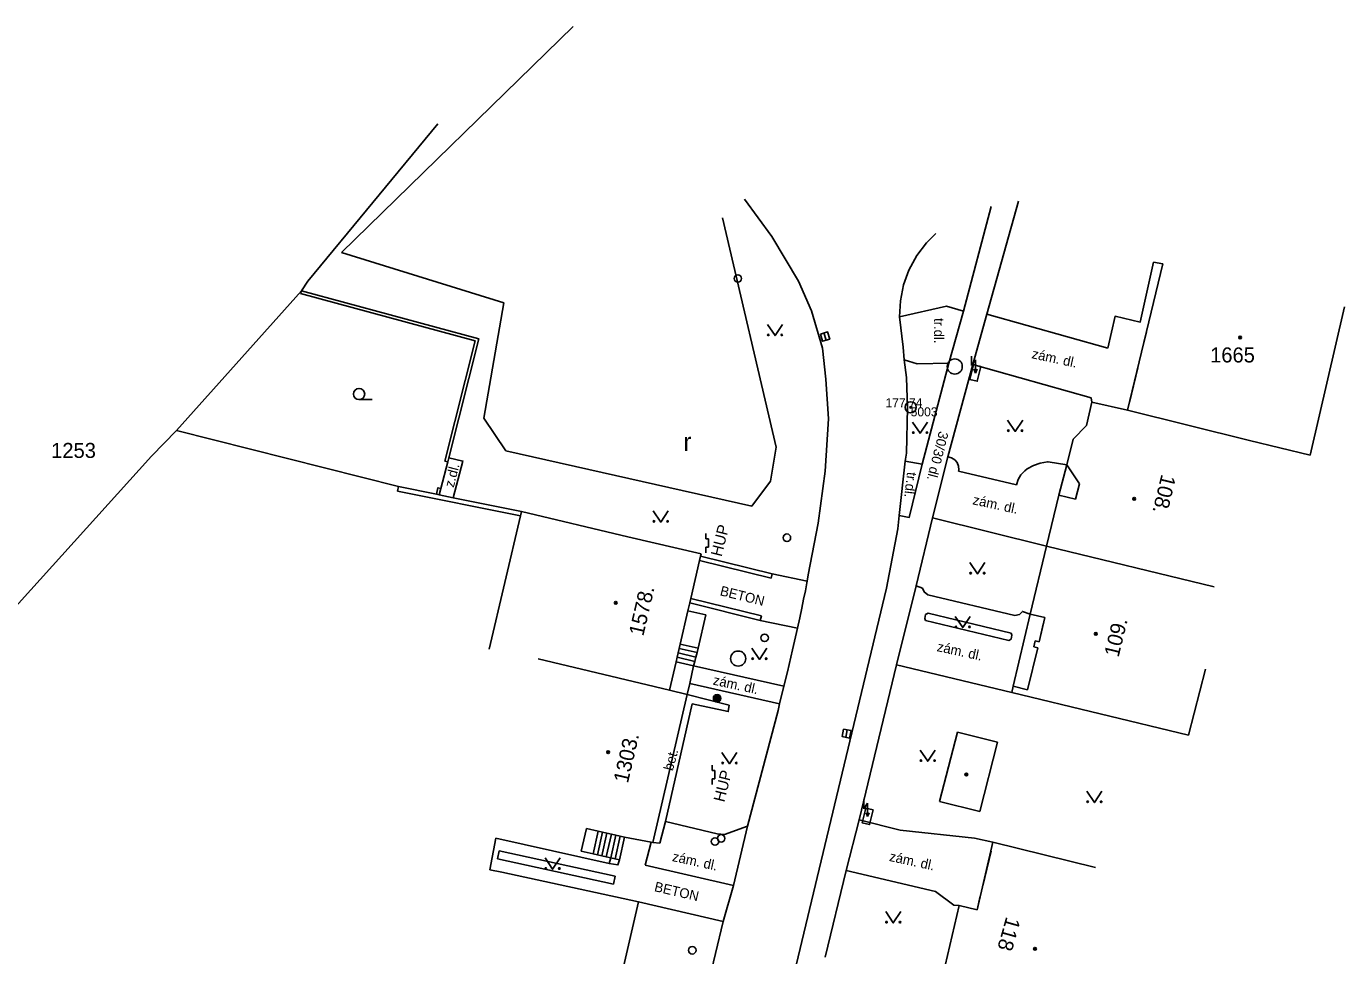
# Model space of a CAD drawing. Extents: x -540235 to -537963, y -1184915 to -1183660.
# Drawn here: x -538224.4 to -538136.8, y -1183806.3 to -1183744.6 of the extents above; entities that cross this region are included whole.
import ezdxf

# ---------------------------------------------------------------- set-up
doc = ezdxf.new("R2010")
doc.units = 0
for name, color, linetype in [('Vrstva 10', 7, 'Continuous'), ('Vrstva 11', 7, 'Continuous'), ('Vrstva 21', 7, 'Continuous'), ('Vrstva 22', 7, 'Continuous'), ('Vrstva 23', 7, 'Continuous'), ('Vrstva 24', 7, 'Continuous'), ('Vrstva 25', 7, 'Continuous'), ('Vrstva 27', 7, 'Continuous'), ('Vrstva 28', 7, 'Continuous'), ('Vrstva 36', 7, 'Continuous'), ('Vrstva 39', 7, 'Continuous'), ('Vrstva 40', 7, 'Continuous'), ('Vrstva 41', 7, 'Continuous'), ('Vrstva 47', 7, 'Continuous'), ('Vrstva 5', 7, 'Continuous'), ('Vrstva 6', 7, 'Continuous'), ('Vrstva 7', 7, 'Continuous'), ('Vrstva 8', 7, 'Continuous')]:
    doc.layers.add(name, color=color, linetype=linetype)

msp = doc.modelspace()

# ---------------------------------------------------------------- linework, layer by layer
at = {"layer": 'Vrstva 10'}
for p, q in [((-538171.1, -1183770.66), (-538171.32, -1183774.15)), ((-538166.39, -1183777.09), (-538165.99, -1183773.49)), ((-538167.23, -1183781.93), (-538173.25, -1183806.97)), ((-538176.48, -1183797.74), (-538177.4, -1183801.69)), ((-538177.4, -1183801.69), (-538178.1, -1183804.07)), ((-538178.1, -1183804.07), (-538180.3, -1183813.22))]:
    msp.add_line(p, q, dxfattribs=at)
for points in [[(-538176.67, -1183756.07), (-538174.86, -1183758.55), (-538173.09, -1183761.51), (-538172.22, -1183763.48)], [(-538166.37, -1183763.88), (-538166.317, -1183762.812), (-538166.105, -1183761.763), (-538165.75, -1183760.78), (-538165.229, -1183759.818), (-538164.584, -1183758.965), (-538163.96, -1183758.34)], [(-538172.22, -1183763.48), (-538171.5, -1183765.96), (-538171.26, -1183768.02), (-538171.1, -1183770.66)], [(-538166.37, -1183763.88), (-538166.14, -1183765.91), (-538166.06, -1183766.75)], [(-538166.06, -1183766.75), (-538165.9, -1183767.91), (-538165.85, -1183769.93), (-538165.91, -1183772.95), (-538165.99, -1183773.49)], [(-538171.32, -1183774.15), (-538171.78, -1183777.6), (-538172.44, -1183781.03)], [(-538166.39, -1183777.09), (-538166.49, -1183777.98), (-538167.23, -1183781.93)], [(-538173.83, -1183787.474), (-538173.493, -1183786.023), (-538173.16, -1183784.57), (-538173.008, -1183783.893), (-538172.87, -1183783.257), (-538172.745, -1183782.661), (-538172.631, -1183782.1), (-538172.527, -1183781.574), (-538172.503, -1183781.45), (-538172.44, -1183781.03)], [(-538174.451, -1183790.053), (-538174.343, -1183789.606), (-538174.06, -1183788.44), (-538173.83, -1183787.474)], [(-538176.48, -1183797.74), (-538174.451, -1183790.053)]]:
    msp.add_lwpolyline(points, dxfattribs=at)
at = {"layer": 'Vrstva 11'}
for p, q in [((-538158.47, -1183756.19), (-538160.57, -1183763.71)), ((-538162.11, -1183763.5), (-538160.29, -1183756.56)), ((-538163.1, -1183766.97), (-538162.11, -1183763.5)), ((-538160.57, -1183763.71), (-538161.5, -1183767.06)), ((-538160.57, -1183763.71), (-538152.53, -1183765.96)), ((-538164.87, -1183773.69), (-538163.1, -1183766.97)), ((-538163.16, -1183773.19), (-538161.5, -1183767.06)), ((-538161.5, -1183767.06), (-538153.63, -1183769.27)), ((-538153.63, -1183769.27), (-538153.59, -1183769.55)), ((-538165.99, -1183773.49), (-538164.87, -1183773.69)), ((-538164.19, -1183777.24), (-538163.16, -1183773.19)), ((-538155.257, -1183773.725), (-538156.49, -1183773.53)), ((-538162.45, -1183774.14), (-538158.6, -1183775.06)), ((-538164.19, -1183777.24), (-538165.27, -1183781.77)), ((-538156.61, -1183779.12), (-538164.19, -1183777.24)), ((-538172.503, -1183781.45), (-538174.83, -1183780.97)), ((-538165.27, -1183781.77), (-538166.57, -1183787.02)), ((-538158.71, -1183783.74), (-538164.48, -1183782.36)), ((-538180.439, -1183783.421), (-538179.24, -1183783.7)), ((-538164.46, -1183783.58), (-538158.94, -1183784.91)), ((-538173.16, -1183784.57), (-538175.63, -1183784.06)), ((-538159.1, -1183785.39), (-538164.64, -1183784.07)), ((-538181.022, -1183785.932), (-538179.835, -1183786.208)), ((-538180.954, -1183785.64), (-538179.767, -1183785.916)), ((-538181.226, -1183786.809), (-538180.06, -1183787.08)), ((-538181.158, -1183786.516), (-538179.971, -1183786.792)), ((-538181.09, -1183786.224), (-538179.903, -1183786.5)), ((-538180.06, -1183787.08), (-538174.06, -1183788.44)), ((-538166.57, -1183787.02), (-538169.06, -1183797.32)), ((-538158.91, -1183788.86), (-538166.57, -1183787.02)), ((-538180.311, -1183788.253), (-538174.343, -1183789.606)), ((-538181.94, -1183797.44), (-538180.16, -1183789.6)), ((-538182.3, -1183798.88), (-538181.94, -1183797.44)), ((-538169.06, -1183797.32), (-538169.93, -1183800.68)), ((-538186.405, -1183798.082), (-538186.745, -1183799.582)), ((-538186.113, -1183798.148), (-538186.453, -1183799.648)), ((-538185.82, -1183798.215), (-538186.16, -1183799.715)), ((-538185.528, -1183798.281), (-538185.868, -1183799.781)), ((-538185.235, -1183798.347), (-538185.575, -1183799.847)), ((-538184.943, -1183798.414), (-538185.283, -1183799.914)), ((-538184.99, -1183799.98), (-538184.65, -1183798.48)), ((-538193.1, -1183799.92), (-538192.98, -1183799.37)), ((-538192.98, -1183799.37), (-538185.28, -1183801.06)), ((-538183.28, -1183800.33), (-538182.89, -1183798.8)), ((-538182.77, -1183798.83), (-538182.3, -1183798.88)), ((-538185.39, -1183801.59), (-538193.1, -1183799.92)), ((-538185.28, -1183801.06), (-538185.39, -1183801.59)), ((-538177.4, -1183801.69), (-538183.28, -1183800.33)), ((-538169.93, -1183800.68), (-538171.31, -1183806.45)), ((-538163.98, -1183802.09), (-538169.93, -1183800.68)), ((-538178.1, -1183804.07), (-538183.72, -1183802.77))]:
    msp.add_line(p, q, dxfattribs=at)
for points in [[(-538152.53, -1183765.96), (-538152.04, -1183763.85), (-538150.37, -1183764.24), (-538149.48, -1183760.26), (-538148.87, -1183760.36)], [(-538166.37, -1183763.88), (-538163.24, -1183763.18), (-538162.11, -1183763.5)], [(-538163.1, -1183766.97), (-538165.21, -1183767.01), (-538166.06, -1183766.75)], [(-538196.34, -1183773.25), (-538195.4, -1183773.47), (-538196.04, -1183775.91)], [(-538166.39, -1183777.09), (-538165.73, -1183777.22), (-538164.87, -1183773.69)], [(-538163.16, -1183773.19), (-538162.917, -1183773.248), (-538162.704, -1183773.38), (-538162.543, -1183773.571), (-538162.451, -1183773.804), (-538162.436, -1183774.053), (-538162.45, -1183774.14)], [(-538157.88, -1183773.99), (-538157.463, -1183773.763), (-538157.014, -1183773.61), (-538156.545, -1183773.534), (-538156.49, -1183773.53)], [(-538158.6, -1183775.06), (-538158.486, -1183774.708), (-538158.299, -1183774.39), (-538158.047, -1183774.118), (-538157.88, -1183773.99)], [(-538164.48, -1183782.36), (-538164.73, -1183782.17), (-538164.85, -1183781.91), (-538165.27, -1183781.77)], [(-538164.64, -1183784.07), (-538164.7, -1183783.93), (-538164.64, -1183783.68), (-538164.46, -1183783.58)], [(-538157.68, -1183783.65), (-538158.2, -1183783.47), (-538158.39, -1183783.67), (-538158.71, -1183783.74)], [(-538179.24, -1183783.7), (-538179.767, -1183785.916), (-538179.835, -1183786.208), (-538179.903, -1183786.5), (-538179.971, -1183786.792), (-538180.06, -1183787.08)], [(-538158.94, -1183784.91), (-538158.9, -1183785.05), (-538158.95, -1183785.3), (-538159.1, -1183785.39)], [(-538180.48, -1183788.98), (-538180.311, -1183788.253), (-538180.06, -1183787.08)], [(-538180.16, -1183789.6), (-538177.76, -1183790.12), (-538177.7, -1183789.7), (-538180.48, -1183788.98)], [(-538176.48, -1183797.74), (-538178, -1183798.3), (-538178.49, -1183798.24), (-538181.94, -1183797.44)], [(-538169.06, -1183797.32), (-538166.33, -1183798), (-538161.38, -1183798.54), (-538160.16, -1183798.8)], [(-538162.41, -1183803.01), (-538162.77, -1183802.99), (-538163.98, -1183802.09)]]:
    msp.add_lwpolyline(points, dxfattribs=at)
at = {"layer": 'Vrstva 21'}
for radius in [0.375, 0.05]:
    msp.add_circle((-538165.63, -1183769.9), radius, dxfattribs=at)
at = {"layer": 'Vrstva 23'}
for p, q in [((-538188.06, -1183744.58), (-538203.46, -1183759.62)), ((-538174.57, -1183772.54), (-538178.14, -1183757.31)), ((-538203.46, -1183759.62), (-538192.67, -1183762.96)), ((-538192.67, -1183762.96), (-538194.01, -1183770.63)), ((-538194.01, -1183770.63), (-538192.55, -1183772.79)), ((-538192.55, -1183772.79), (-538176.19, -1183776.48))]:
    msp.add_line(p, q, dxfattribs=at)
msp.add_lwpolyline([(-538176.19, -1183776.48), (-538174.94, -1183774.81), (-538174.57, -1183772.54)], dxfattribs=at)
at = {"layer": 'Vrstva 24'}
for p, q in [((-538161.58, -1183766.494), (-538161.58, -1183767.12)), ((-538161.58, -1183767.12), (-538161.33, -1183766.745)), ((-538161.33, -1183766.745), (-538161.33, -1183767.62)), ((-538161.44, -1183767.375), (-538161.33, -1183767.62)), ((-538161.33, -1183767.62), (-538161.22, -1183767.375)), ((-538179.249, -1183778.649), (-538179.25, -1183778.281)), ((-538179.25, -1183779.57), (-538179.249, -1183779.202)), ((-538179.066, -1183778.65), (-538179.249, -1183778.649)), ((-538179.249, -1183779.202), (-538179.066, -1183779.202)), ((-538179.066, -1183779.202), (-538179.066, -1183778.65)), ((-538178.829, -1183794.049), (-538178.83, -1183793.681)), ((-538178.646, -1183794.05), (-538178.829, -1183794.049)), ((-538178.646, -1183794.602), (-538178.646, -1183794.05)), ((-538178.83, -1183794.97), (-538178.829, -1183794.602)), ((-538178.829, -1183794.602), (-538178.646, -1183794.602)), ((-538168.74, -1183795.964), (-538168.74, -1183796.59)), ((-538168.74, -1183796.59), (-538168.49, -1183796.215)), ((-538168.49, -1183796.215), (-538168.49, -1183797.09)), ((-538168.6, -1183796.845), (-538168.49, -1183797.09)), ((-538168.49, -1183797.09), (-538168.38, -1183796.845))]:
    msp.add_line(p, q, dxfattribs=at)
for points in [[(-538161.453, -1183767.075), (-538161.692, -1183768.046), (-538161.207, -1183768.165), (-538160.968, -1183767.194)], [(-538168.619, -1183796.546), (-538168.848, -1183797.519), (-538168.361, -1183797.634), (-538168.132, -1183796.661)]]:
    msp.add_lwpolyline(points, close=True, dxfattribs=at)
at = {"layer": 'Vrstva 25'}
for radius in [0.25, 0.2, 0.15, 0.1, 0.05]:
    msp.add_circle((-538178.5, -1183789.24), radius, dxfattribs=at)
at = {"layer": 'Vrstva 27'}
for p, q in [((-538171.396, -1183764.96), (-538171.244, -1183765.436)), ((-538169.843, -1183791.344), (-538169.937, -1183791.836))]:
    msp.add_line(p, q, dxfattribs=at)
for points in [[(-538171.634, -1183765.036), (-538171.482, -1183765.512), (-538171.006, -1183765.36), (-538171.158, -1183764.884)], [(-538170.088, -1183791.297), (-538170.183, -1183791.788), (-538169.692, -1183791.883), (-538169.597, -1183791.392)]]:
    msp.add_lwpolyline(points, close=True, dxfattribs=at)
for centre in [(-538162.699, -1183767.188), (-538177.1, -1183786.6)]:
    msp.add_circle(centre, 0.5, dxfattribs=at)
at = {"layer": 'Vrstva 28'}
for centre in [(-538177.12, -1183761.34), (-538173.86, -1183778.57), (-538175.34, -1183785.22), (-538178.23, -1183798.55), (-538178.64, -1183798.76), (-538180.15, -1183805.99)]:
    msp.add_circle(centre, 0.25, dxfattribs=at)
at = {"layer": 'Vrstva 36'}
msp.add_line((-538202.303, -1183769.391), (-538201.428, -1183769.391), dxfattribs=at)
for points in [[(-538175.149, -1183764.385), (-538174.649, -1183765.135), (-538174.149, -1183764.385)], [(-538165.502, -1183770.878), (-538165.002, -1183771.628), (-538164.502, -1183770.878)], [(-538159.183, -1183770.754), (-538158.683, -1183771.504), (-538158.183, -1183770.754)], [(-538182.743, -1183776.783), (-538182.243, -1183777.533), (-538181.743, -1183776.783)], [(-538161.695, -1183780.222), (-538161.195, -1183780.972), (-538160.695, -1183780.222)], [(-538162.669, -1183783.795), (-538162.169, -1183784.545), (-538161.669, -1183783.795)], [(-538176.188, -1183785.911), (-538175.688, -1183786.661), (-538175.188, -1183785.911)], [(-538178.177, -1183792.846), (-538177.677, -1183793.596), (-538177.177, -1183792.846)], [(-538164.992, -1183792.678), (-538164.492, -1183793.428), (-538163.992, -1183792.678)], [(-538153.915, -1183795.42), (-538153.415, -1183796.17), (-538152.915, -1183795.42)], [(-538189.938, -1183799.853), (-538189.438, -1183800.603), (-538188.938, -1183799.853)], [(-538167.286, -1183803.42), (-538166.786, -1183804.17), (-538166.286, -1183803.42)]]:
    msp.add_lwpolyline(points, dxfattribs=at)
for centre, radius in [((-538175.0992, -1183765.0848), 0.05), ((-538174.1998, -1183765.0848), 0.05), ((-538202.3031, -1183769.0159), 0.375), ((-538165.4522, -1183771.5778), 0.05), ((-538164.5528, -1183771.5778), 0.05), ((-538159.1332, -1183771.4538), 0.05), ((-538158.2338, -1183771.4538), 0.05), ((-538182.6932, -1183777.4828), 0.05), ((-538181.7938, -1183777.4828), 0.05), ((-538161.6452, -1183780.9218), 0.05), ((-538160.7458, -1183780.9218), 0.05), ((-538162.6192, -1183784.4948), 0.05), ((-538161.7198, -1183784.4948), 0.05), ((-538176.1382, -1183786.6108), 0.05), ((-538175.2388, -1183786.6108), 0.05), ((-538178.1272, -1183793.5458), 0.05), ((-538177.2278, -1183793.5458), 0.05), ((-538164.9422, -1183793.3778), 0.05), ((-538164.0428, -1183793.3778), 0.05), ((-538153.8652, -1183796.1198), 0.05), ((-538152.9658, -1183796.1198), 0.05), ((-538189.8882, -1183800.5528), 0.05), ((-538188.9888, -1183800.5528), 0.05), ((-538167.2362, -1183804.1198), 0.05), ((-538166.3368, -1183804.1198), 0.05)]:
    msp.add_circle(centre, radius, dxfattribs=at)
at = {"layer": 'Vrstva 39'}
for centre, radius in [((-538143.729, -1183765.267), 0.09), ((-538143.729, -1183765.267), 0.0398), ((-538150.765, -1183775.983), 0.09), ((-538150.765, -1183775.983), 0.0398), ((-538185.241, -1183782.892), 0.09), ((-538185.241, -1183782.892), 0.0398), ((-538153.328, -1183784.961), 0.09), ((-538153.328, -1183784.961), 0.0398), ((-538185.748, -1183792.826), 0.09), ((-538185.748, -1183792.826), 0.0398), ((-538161.93, -1183794.312), 0.09), ((-538161.93, -1183794.312), 0.0398), ((-538157.366, -1183805.892), 0.09), ((-538157.366, -1183805.892), 0.0398)]:
    msp.add_circle(centre, radius, dxfattribs=at)
at = {"layer": 'Vrstva 5'}
for p, q in [((-538148.87, -1183760.36), (-538151.21, -1183770.09)), ((-538139.07, -1183773.09), (-538136.78, -1183763.22)), ((-538153.942, -1183771.103), (-538153.59, -1183769.55)), ((-538153.59, -1183769.55), (-538151.21, -1183770.09)), ((-538151.21, -1183770.09), (-538143.1, -1183772.11)), ((-538154.82, -1183772.02), (-538153.942, -1183771.103)), ((-538154.82, -1183772.02), (-538155.257, -1183773.725)), ((-538143.1, -1183772.11), (-538139.07, -1183773.09)), ((-538155.77, -1183775.73), (-538155.257, -1183773.725)), ((-538155.257, -1183773.725), (-538154.411, -1183774.979)), ((-538155.77, -1183775.73), (-538156.61, -1183779.12)), ((-538154.675, -1183776.01), (-538155.77, -1183775.73)), ((-538193.66, -1183785.98), (-538191.575, -1183777.112)), ((-538191.575, -1183777.112), (-538191.5, -1183776.82)), ((-538191.5, -1183776.82), (-538184.43, -1183778.508)), ((-538184.43, -1183778.508), (-538179.56, -1183779.64)), ((-538156.61, -1183779.12), (-538157.68, -1183783.65)), ((-538145.45, -1183781.83), (-538156.61, -1183779.12)), ((-538180.249, -1183782.602), (-538179.662, -1183780.078)), ((-538179.662, -1183780.078), (-538179.593, -1183779.786)), ((-538179.593, -1183779.786), (-538179.56, -1183779.64)), ((-538180.317, -1183782.895), (-538180.249, -1183782.602)), ((-538180.954, -1183785.64), (-538180.439, -1183783.421)), ((-538180.439, -1183783.421), (-538180.317, -1183782.895)), ((-538156.707, -1183783.88), (-538157.68, -1183783.65)), ((-538157.08, -1183785.49), (-538156.707, -1183783.88)), ((-538181.09, -1183786.224), (-538181.022, -1183785.932)), ((-538181.022, -1183785.932), (-538180.954, -1183785.64)), ((-538157.86, -1183788.67), (-538157.167, -1183785.891)), ((-538157.44, -1183785.83), (-538157.35, -1183785.43)), ((-538157.167, -1183785.891), (-538157.44, -1183785.83)), ((-538157.35, -1183785.43), (-538157.08, -1183785.49)), ((-538190.39, -1183786.62), (-538181.667, -1183788.704)), ((-538181.667, -1183788.704), (-538181.226, -1183786.809)), ((-538181.226, -1183786.809), (-538181.158, -1183786.516)), ((-538181.158, -1183786.516), (-538181.09, -1183786.224)), ((-538147.15, -1183791.69), (-538146.04, -1183787.3)), ((-538181.667, -1183788.704), (-538180.48, -1183788.98)), ((-538158.812, -1183788.445), (-538157.86, -1183788.67)), ((-538182.77, -1183798.83), (-538180.48, -1183788.98)), ((-538158.91, -1183788.86), (-538147.15, -1183791.69)), ((-538162.52, -1183791.5), (-538163.71, -1183796.11)), ((-538159.85, -1183792.16), (-538162.52, -1183791.5)), ((-538161.04, -1183796.77), (-538159.85, -1183792.16)), ((-538163.71, -1183796.11), (-538161.04, -1183796.77)), ((-538187.526, -1183799.405), (-538187.186, -1183797.905)), ((-538187.186, -1183797.905), (-538186.405, -1183798.082)), ((-538186.113, -1183798.148), (-538186.405, -1183798.082)), ((-538185.82, -1183798.215), (-538186.113, -1183798.148)), ((-538185.528, -1183798.281), (-538185.82, -1183798.215)), ((-538185.235, -1183798.347), (-538185.528, -1183798.281)), ((-538184.943, -1183798.414), (-538185.235, -1183798.347)), ((-538184.65, -1183798.48), (-538184.943, -1183798.414)), ((-538184.65, -1183798.48), (-538182.89, -1183798.8)), ((-538185.67, -1183800.22), (-538193.2, -1183798.54)), ((-538182.89, -1183798.8), (-538182.77, -1183798.83)), ((-538160.16, -1183798.8), (-538161.22, -1183803.291)), ((-538153.35, -1183800.49), (-538160.16, -1183798.8)), ((-538186.745, -1183799.582), (-538187.526, -1183799.405)), ((-538186.453, -1183799.648), (-538186.745, -1183799.582)), ((-538186.16, -1183799.715), (-538186.453, -1183799.648)), ((-538185.868, -1183799.781), (-538186.16, -1183799.715)), ((-538185.575, -1183799.847), (-538185.868, -1183799.781)), ((-538185.575, -1183799.847), (-538185.67, -1183800.22)), ((-538192.82, -1183800.8), (-538183.72, -1183802.77)), ((-538162.41, -1183803.01), (-538163.66, -1183808.33)), ((-538161.22, -1183803.291), (-538162.41, -1183803.01))]:
    msp.add_line(p, q, dxfattribs=at)
for points in [[(-538157.68, -1183783.65), (-538158.812, -1183788.445)], [(-538158.812, -1183788.445), (-538158.91, -1183788.86)], [(-538183.72, -1183802.77), (-538185.84, -1183811.89)]]:
    msp.add_lwpolyline(points, dxfattribs=at)
at = {"layer": 'Vrstva 6'}
for p, q in [((-538149.96, -1183764.91), (-538150.21, -1183765.94)), ((-538150.53, -1183767.27), (-538151.09, -1183769.58)), ((-538154.411, -1183774.979), (-538154.675, -1183776.01)), ((-538156.79, -1183784.23), (-538157.08, -1183785.49)), ((-538157.167, -1183785.891), (-538157.86, -1183788.67)), ((-538160.29, -1183799.4), (-538160.83, -1183801.7)), ((-538161.01, -1183802.4), (-538161.22, -1183803.291))]:
    msp.add_line(p, q, dxfattribs=at)
at = {"layer": 'Vrstva 7'}
for p, q in [((-538197.074, -1183751.062), (-538205.71, -1183761.51)), ((-538206.14, -1183762.15), (-538205.71, -1183761.51)), ((-538214.45, -1183771.45), (-538206.14, -1183762.15)), ((-538206.14, -1183762.15), (-538206.192, -1183762.343)), ((-538206.192, -1183762.343), (-538194.592, -1183765.482)), ((-538206.14, -1183762.15), (-538194.35, -1183765.34)), ((-538194.592, -1183765.482), (-538196.604, -1183773.471)), ((-538194.35, -1183765.34), (-538196.34, -1183773.25)), ((-538214.45, -1183771.45), (-538216.1, -1183773.14)), ((-538199.687, -1183775.174), (-538214.45, -1183771.45)), ((-538216.1, -1183773.14), (-538306.52, -1183873.14)), ((-538196.604, -1183773.471), (-538196.41, -1183773.52)), ((-538196.34, -1183773.25), (-538196.41, -1183773.52)), ((-538199.687, -1183775.174), (-538199.746, -1183775.468)), ((-538199.746, -1183775.468), (-538191.575, -1183777.112)), ((-538196.87, -1183775.29), (-538196.97, -1183775.72)), ((-538174.902, -1183781.261), (-538179.662, -1183780.078)), ((-538174.83, -1183780.97), (-538179.593, -1183779.786)), ((-538174.902, -1183781.261), (-538174.83, -1183780.97)), ((-538175.557, -1183783.768), (-538180.249, -1183782.602)), ((-538175.63, -1183784.06), (-538180.317, -1183782.895)), ((-538175.63, -1183784.06), (-538175.557, -1183783.768)), ((-538193.62, -1183800.65), (-538192.82, -1183800.8))]:
    msp.add_line(p, q, dxfattribs=at)
for points in [[(-538196.97, -1183775.72), (-538197.165, -1183775.675), (-538199.687, -1183775.174)], [(-538196.87, -1183775.29), (-538197.065, -1183775.245), (-538197.165, -1183775.675)], [(-538191.5, -1183776.82), (-538196.04, -1183775.91), (-538196.97, -1183775.72)], [(-538185.67, -1183800.22), (-538185.09, -1183800.32), (-538184.99, -1183799.98)], [(-538184.99, -1183799.98), (-538185.283, -1183799.914), (-538185.575, -1183799.847)]]:
    msp.add_lwpolyline(points, dxfattribs=at)
at = {"layer": 'Vrstva 8'}
for p, q in [((-538196.87, -1183775.29), (-538196.41, -1183773.52)), ((-538193.62, -1183800.65), (-538193.2, -1183798.54))]:
    msp.add_line(p, q, dxfattribs=at)

# ---------------------------------------------------------------- texts
at = {"layer": 'Vrstva 22'}
msp.add_text('177.74', height=0.6, dxfattribs=at).set_placement((-538167.305, -1183769.9))
at = {"layer": 'Vrstva 23'}
msp.add_text('5003', height=0.6, dxfattribs=at).set_placement((-538165.63, -1183770.5))
at = {"layer": 'Vrstva 36'}
msp.add_text('r', height=1.2, dxfattribs=at).set_placement((-538180.739, -1183772.793))
at = {"layer": 'Vrstva 40'}
for s, rotation, p in [('tr.dl.', 270, (-538164.069, -1183763.966)), ('zám. dl.', 347.772894, (-538157.622, -1183766.631)), ('30/30 dl.', 255.726011, (-538163.741, -1183771.452)), ('z.dl.', 75.636336, (-538196.013, -1183775.268)), ('tr.dl.', 263.455728, (-538165.866, -1183774.181)), ('zám. dl.', 347.772894, (-538161.546, -1183776.343)), ('BETON', 346.044236, (-538178.348, -1183782.386)), ('zám. dl.', 347.772894, (-538163.923, -1183786.099)), ('zám. dl.', 347.772894, (-538178.817, -1183788.324)), ('bet.', 75.008458, (-538181.445, -1183794.102)), ('zám. dl.', 347.772894, (-538181.524, -1183800.052)), ('zám. dl.', 347.772894, (-538167.095, -1183800.044)), ('BETON', 346.914333, (-538182.716, -1183802.053))]:
    msp.add_text(s, height=0.65, rotation=rotation, dxfattribs=at).set_placement(p)
at = {"layer": 'Vrstva 41'}
for p in [(-538178.201, -1183779.866), (-538178.023, -1183796.182)]:
    msp.add_text('HUP', height=0.75, rotation=75.985808, dxfattribs=at).set_placement(p)
at = {"layer": 'Vrstva 47'}
for s, p in [('1665', (-538145.722, -1183766.92)), ('1253', (-538222.773, -1183773.266))]:
    msp.add_text(s, height=1, dxfattribs=at).set_placement(p)
for s, rotation, p in [('108.', 256.473233, (-538148.954, -1183774.31)), ('1578.', 76.913547, (-538183.409, -1183785.155)), ('109.', 76.258092, (-538151.813, -1183786.557)), ('1303.', 76.911958, (-538184.43, -1183794.931)), ('118', 254.281439, (-538159.273, -1183803.714))]:
    msp.add_text(s, height=1, rotation=rotation, dxfattribs=at).set_placement(p)

doc.saveas('drawing.dxf')
